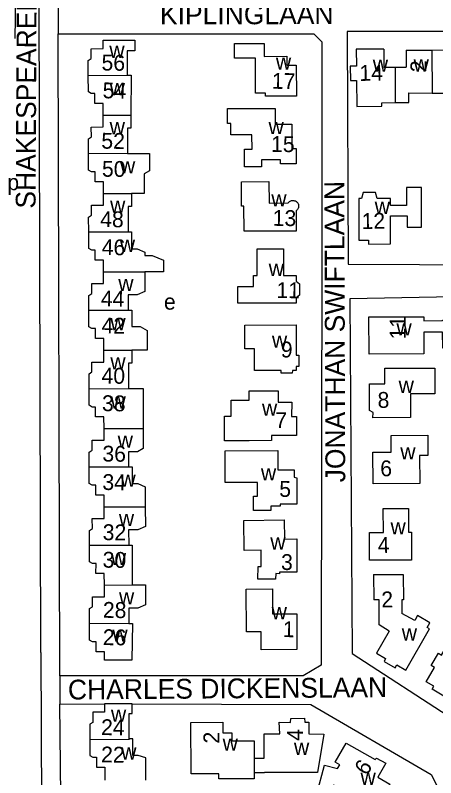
# Model space of a CAD drawing. Extents: x 159441 to 162086, y 388175 to 389787.
# Drawn here: x 161032.2 to 161138.4, y 388501.9 to 388694.6 of the extents above; entities that cross this region are included whole.
import ezdxf

# ---------------------------------------------------------------- set-up
doc = ezdxf.new("R2010")
doc.units = 0
for name, color, linetype in [('BLT_Basislijn', 7, 'Continuous'), ('BLT_Bebouwing', 7, 'Continuous'), ('BLT_Centroide', 7, 'Continuous'), ('BLT_Huisnummer', 7, 'Continuous'), ('BLT_Huisnummer_ tussenligend', 7, 'Continuous'), ('BLT_Onderverdeling_panden', 7, 'Continuous'), ('BLT_Straatnaam', 7, 'Continuous'), ('BLT_Vlakafsluiter', 7, 'Continuous')]:
    doc.layers.add(name, color=color, linetype=linetype)

msp = doc.modelspace()

# ---------------------------------------------------------------- linework, layer by layer
at = {"layer": 'BLT_Basislijn'}
for p, q in [((161032.19, 388688.74), (161032.58, 388714.86)), ((161043.47, 388527.69), (161043.09, 388689.87)), ((161116.02, 388690.48), (161116.31, 388631.73)), ((161165.42, 388623.86), (161116.75, 388622.95)), ((161116.75, 388622.95), (161117.32, 388533.33)), ((161117.32, 388533.33), (161143.65, 388516.17)), ((161043.5, 388520.52), (161054.79, 388520.57)), ((161044.45, 388412.36), (161043.5, 388520.52)), ((161061.74, 388520.59), (161106.86, 388520.45))]:
    msp.add_line(p, q, dxfattribs=at)
for points in [[(161038.68, 388533.55), (161038.25, 388699.64)], [(161043.09, 388689.87), (161107.6, 388689.92), (161109.66, 388687.86), (161109.66, 388636.57)], [(161245.45, 388564.44), (161304.37, 388593.21), (161306.09, 388596.99), (161283.75, 388641.67), (161183.73, 388690.48), (161116.02, 388690.48)], [(161109.66, 388636.57), (161109.49, 388530.39), (161104.96, 388527.66), (161043.47, 388527.69)], [(161116.31, 388631.73), (161170.26, 388631.42), (161224.37, 388604.8), (161245.45, 388564.44)], [(161038.68, 388533.55), (161039.27, 388397.68), (161039.46, 388396.05)], [(161106.86, 388520.45), (161137.31, 388502.69), (161149.7, 388477.9)]]:
    msp.add_lwpolyline(points, dxfattribs=at)
at = {"layer": 'BLT_Bebouwing'}
for p, q in [((161125.32, 388686.07), (161118.36, 388686.03)), ((161125.32, 388686.07), (161125.35, 388681.47)), ((161130.96, 388685.78), (161137.45, 388685.81)), ((161130.96, 388685.78), (161130.99, 388681.49)), ((161137.45, 388685.81), (161143.93, 388685.83)), ((161125.35, 388681.47), (161128.17, 388681.48)), ((161128.17, 388681.48), (161130.99, 388681.49)), ((161089.23, 388671.04), (161097.9, 388671.06)), ((161064.8, 388649.55), (161061.54, 388649.54)), ((161103.17, 388645.2), (161103.17, 388640.05)), ((161122.73, 388553.26), (161122.75, 388546.86)), ((161061.74, 388550.62), (161065.08, 388550.63)), ((161076.63, 388502.89), (161076.59, 388515.86)), ((161092.58, 388506.89), (161095.06, 388506.89)), ((161092.59, 388503.26), (161095.13, 388503.26))]:
    msp.add_line(p, q, dxfattribs=at)
for points in [[(161050.66, 388679.4), (161050.65, 388683.18), (161051.4, 388683.64), (161051.39, 388686.15), (161054.38, 388686.17), (161054.38, 388688.28), (161062.42, 388688.29), (161062.43, 388685.62), (161060.5, 388685.61), (161060.51, 388679.42)], [(161087.58, 388687.48), (161095.09, 388687.5), (161095.1, 388684.18), (161100.81, 388684.22), (161100.85, 388681.95), (161103.21, 388681.98), (161103.26, 388674.19), (161095.45, 388674.17), (161095.44, 388674.94), (161092.9, 388674.93), (161092.86, 388683.78), (161087.57, 388683.76), (161087.58, 388687.48)], [(161118.36, 388686.03), (161118.37, 388681.75), (161116.84, 388681.75), (161116.86, 388678.13), (161118.39, 388678.15), (161118.46, 388671.54)], [(161054.43, 388669.38), (161054.42, 388672.28), (161052.3, 388672.26), (161052.32, 388674.79), (161051.42, 388674.79), (161050.67, 388675.24), (161050.66, 388679.4)], [(161060.51, 388679.42), (161061.45, 388679.43), (161061.43, 388669.39)], [(161128.2, 388672.54), (161131.67, 388672.57), (161131.65, 388674.97), (161137.49, 388674.95)], [(161137.49, 388674.95), (161143.38, 388674.92), (161143.39, 388672.52), (161146.97, 388672.53)], [(161118.46, 388671.54), (161124.82, 388671.6), (161124.81, 388672.51), (161128.2, 388672.54)], [(161097.9, 388671.06), (161097.87, 388667.07), (161102.08, 388667.08), (161102.1, 388660.93), (161103.14, 388660.93), (161103.14, 388657.03), (161099.24, 388657.03), (161099.24, 388658.08), (161094.45, 388658.08), (161094.45, 388656.27), (161090.15, 388656.27), (161090.15, 388660.77), (161092.02, 388660.77), (161091.99, 388664.4), (161086.69, 388664.36), (161086.68, 388667.28), (161085.82, 388667.28), (161085.81, 388671.03), (161089.23, 388671.04)], [(161050.71, 388659.72), (161050.7, 388663.39), (161051.45, 388663.85), (161051.41, 388666.36), (161054.44, 388666.37), (161054.43, 388669.38)], [(161061.43, 388669.39), (161061.42, 388666.06), (161060.56, 388666.06), (161060.57, 388659.63)], [(161054.48, 388649.58), (161054.47, 388652.5), (161052.38, 388652.49), (161052.37, 388655.01), (161051.47, 388655.01), (161050.72, 388655.46), (161050.71, 388659.72)], [(161060.57, 388659.63), (161061.47, 388659.63), (161066.14, 388659.65), (161066.15, 388655.3), (161064.8, 388654.55), (161064.8, 388649.55)], [(161089.33, 388652.54), (161096.3, 388652.55), (161096.31, 388647.14), (161101.18, 388647.18), (161101.33, 388647.36), (161101.48, 388647.5), (161101.62, 388647.6), (161101.78, 388647.67), (161101.96, 388647.75), (161102.15, 388647.79), (161102.33, 388647.8), (161102.57, 388647.79), (161102.79, 388647.73), (161102.96, 388647.67), (161103.1, 388647.6), (161103.22, 388647.53), (161103.36, 388647.39), (161103.47, 388647.27), (161103.6, 388647.09), (161103.64, 388646.99), (161103.73, 388646.8), (161103.77, 388646.62), (161103.78, 388646.48), (161103.79, 388646.3), (161103.75, 388646.1), (161103.73, 388645.96), (161103.67, 388645.81), (161103.59, 388645.67), (161103.49, 388645.5), (161103.42, 388645.42), (161103.34, 388645.33), (161103.26, 388645.27), (161103.17, 388645.2)], [(161103.17, 388640.05), (161090, 388640), (161089.99, 388646.39), (161089.34, 388646.39), (161089.33, 388652.54)], [(161050.76, 388639.83), (161050.75, 388643.6), (161051.5, 388644.06), (161051.49, 388646.58), (161054.49, 388646.59), (161054.48, 388649.58)], [(161061.54, 388649.54), (161061.55, 388646.29), (161060.69, 388646.28), (161060.7, 388639.86)], [(161131.04, 388646.53), (161126.97, 388646.51), (161126.96, 388648.31), (161123.61, 388648.3), (161123.22, 388649.83), (161120.1, 388649.83), (161119.7, 388648.3), (161118.99, 388648.26), (161119.02, 388637.74)], [(161121.46, 388636.77), (161127.01, 388636.82), (161127.02, 388643.88), (161131.21, 388643.87), (161131.2, 388641.05), (161134.84, 388641.04), (161134.86, 388651.05), (161131.05, 388651.05), (161131.04, 388646.53)], [(161054.53, 388629.78), (161054.52, 388632.7), (161052.43, 388632.7), (161052.42, 388635.22), (161051.52, 388635.21), (161050.77, 388635.66), (161050.76, 388639.83)], [(161060.7, 388639.86), (161061.6, 388639.86), (161061.6, 388635.61), (161063.02, 388635.61), (161064.92, 388634.76), (161064.92, 388633.9), (161066.83, 388633.87), (161069.63, 388632.68), (161069.63, 388629.78), (161064.93, 388629.8)], [(161119.02, 388637.74), (161121.44, 388637.75), (161121.46, 388636.77)], [(161093.31, 388635.58), (161099.95, 388635.59), (161099.96, 388628.85), (161103.18, 388628.86), (161103.18, 388627.37), (161104.05, 388626.75), (161104.04, 388623.84), (161103.18, 388623.2), (161103.18, 388621.86), (161088.44, 388621.82), (161088.43, 388626.02), (161092.43, 388626.03), (161092.42, 388628.82), (161093.33, 388628.82), (161093.31, 388635.58)], [(161050.81, 388620.03), (161050.8, 388623.8), (161051.55, 388624.25), (161051.52, 388626.78), (161054.54, 388626.77), (161054.53, 388629.78)], [(161064.93, 388629.8), (161064.94, 388624.77), (161063.03, 388623.91), (161060.73, 388623.91), (161060.74, 388620.05)], [(161054.58, 388609.98), (161054.57, 388612.88), (161052.47, 388612.88), (161052.47, 388615.4), (161051.57, 388615.4), (161050.82, 388615.85), (161050.81, 388620.03)], [(161060.74, 388620.05), (161061.64, 388620.05), (161061.64, 388615.91), (161063.8, 388615.92), (161065.56, 388614.93), (161065.56, 388610), (161061.64, 388609.99)], [(161121.56, 388618.35), (161135.4, 388618.4), (161135.42, 388617.41), (161140.14, 388617.44), (161140.15, 388617.56), (161146.29, 388617.58), (161146.32, 388610.54), (161140.18, 388610.51), (161140.16, 388614.54), (161135.43, 388614.52), (161135.45, 388609.07), (161121.61, 388608.99), (161121.56, 388618.35)], [(161090.22, 388616.31), (161103.2, 388616.33), (161103.2, 388608.74), (161103.88, 388608.72), (161103.88, 388605.86), (161103.21, 388605.85), (161103.2, 388604.85), (161102.22, 388604.85), (161102.19, 388604.15), (161099.34, 388604.15), (161099.34, 388604.84), (161092.62, 388604.82), (161092.61, 388610.32), (161090.21, 388610.31), (161090.22, 388616.31)], [(161050.85, 388600.23), (161050.85, 388603.99), (161051.59, 388604.45), (161051.59, 388606.97), (161054.59, 388606.97), (161054.58, 388609.98)], [(161061.64, 388609.99), (161061.64, 388606.68), (161060.78, 388606.67), (161060.79, 388600.25)], [(161125.55, 388605.42), (161138.19, 388605.43), (161138.19, 388598.94), (161132.05, 388598.93), (161132.06, 388592.94), (161122.57, 388592.89), (161122.58, 388594.18), (161121.67, 388594.73), (161121.67, 388601.42), (161122.55, 388601.42), (161125.55, 388601.43), (161125.55, 388605.42)], [(161054.63, 388590.18), (161054.62, 388593.09), (161052.5, 388593.09), (161052.52, 388595.6), (161051.62, 388595.6), (161050.86, 388596.05), (161050.85, 388600.23)], [(161060.79, 388600.25), (161064.5, 388600.25), (161064.52, 388590.2)], [(161091.27, 388587.09), (161085.03, 388587.08), (161085.03, 388593.25), (161086.79, 388593.25), (161086.79, 388597.31), (161091.27, 388597.33), (161091.26, 388599.67), (161098.65, 388599.68), (161098.66, 388596.79), (161102.05, 388596.8), (161102.03, 388593.2), (161103.23, 388593.18), (161103.23, 388588.39), (161096.93, 388588.4), (161096.94, 388587.1), (161091.27, 388587.09)], [(161050.9, 388580.44), (161050.89, 388584.2), (161051.64, 388584.65), (161051.64, 388587.18), (161054.63, 388587.18), (161054.63, 388590.18)], [(161064.52, 388590.2), (161064.52, 388585.1), (161063.1, 388584.3), (161060.84, 388584.3), (161060.84, 388580.47)], [(161127.15, 388584.2), (161127.17, 388588.43), (161136.4, 388588.46), (161136.41, 388583.36), (161134.35, 388583.35), (161134.37, 388576.3), (161122.58, 388576.19), (161122.51, 388584.16), (161127.15, 388584.2)], [(161085.23, 388584.54), (161098.54, 388584.58), (161098.55, 388579.74), (161102.69, 388579.74), (161102.7, 388577.87), (161103.3, 388577.68), (161103.3, 388571.05), (161099.14, 388571.04), (161099.14, 388570.54), (161096.78, 388570.53), (161096.78, 388569.47), (161092.36, 388569.47), (161092.35, 388573.1), (161093.41, 388573.1), (161093.4, 388576.52), (161085.25, 388576.49), (161085.23, 388584.54)], [(161054.67, 388570.38), (161054.67, 388573.31), (161052.57, 388573.3), (161052.56, 388575.82), (161051.66, 388575.82), (161050.91, 388576.27), (161050.9, 388580.44)], [(161060.84, 388580.47), (161061.74, 388580.47), (161061.74, 388576.24), (161063.15, 388576.24), (161065.05, 388575.39), (161065.06, 388570.4)], [(161065.06, 388570.4), (161065.07, 388565.4), (161063.16, 388564.54), (161060.85, 388564.54), (161060.86, 388560.7)], [(161050.95, 388560.68), (161050.94, 388564.41), (161051.69, 388564.89), (161051.66, 388567.4), (161054.68, 388567.4), (161054.67, 388570.38)], [(161125.18, 388569.92), (161131.51, 388569.93), (161131.51, 388563.93), (161132.31, 388563.93), (161132.31, 388556.93), (161121.71, 388556.92), (161121.7, 388563.9), (161125.23, 388563.91), (161125.18, 388569.92)], [(161089.94, 388566.93), (161100.14, 388567.1), (161100.2, 388562.2), (161103.31, 388562.28), (161103.33, 388553.84), (161098.95, 388553.83), (161098.96, 388553.48), (161098.02, 388553.49), (161097.96, 388552.11), (161093.49, 388552.09), (161093.53, 388555.33), (161094.35, 388555.33), (161094.3, 388559.41), (161090.03, 388559.36), (161089.94, 388566.93)], [(161054.72, 388550.58), (161054.71, 388553.53), (161052.6, 388553.52), (161052.61, 388556.04), (161051.71, 388556.04), (161050.96, 388556.49), (161050.95, 388560.68)], [(161060.86, 388560.7), (161061.76, 388560.7), (161061.74, 388550.62)], [(161122.73, 388553.26), (161130.22, 388553.28), (161130.24, 388546.88), (161129.89, 388546.88), (161129.89, 388543.44)], [(161050.99, 388540.79), (161050.99, 388544.65), (161051.74, 388545.1), (161051.71, 388547.61), (161054.73, 388547.62), (161054.72, 388550.58)], [(161065.08, 388550.63), (161065.09, 388545.63), (161063.19, 388544.76), (161060.88, 388544.76), (161060.89, 388540.92)], [(161090.58, 388549.58), (161097.18, 388549.61), (161097.2, 388543.3), (161103.31, 388543.32), (161103.35, 388534.33), (161094.35, 388534.27), (161094.3, 388538.78), (161090.61, 388538.76), (161090.58, 388549.58)], [(161126.7, 388538.98), (161124.12, 388540.53), (161124.1, 388546.85), (161122.75, 388546.86)], [(161126.7, 388538.98), (161123.49, 388533.35), (161125.76, 388532.06), (161125.38, 388531.31), (161128.18, 388529.69), (161128.6, 388530.41), (161130.88, 388529.13), (161136.84, 388539.55), (161136.27, 388539.87), (161136.97, 388541.09), (161133.85, 388542.87), (161133.16, 388541.66), (161129.89, 388543.44)], [(161060.89, 388540.92), (161061.79, 388540.92), (161061.7, 388531.66), (161054.77, 388531.61), (161054.77, 388533.73), (161052.65, 388533.72), (161052.66, 388536.26), (161051.76, 388536.26), (161051, 388536.7), (161050.99, 388540.79)], [(161142.91, 388522.15), (161140.95, 388523.28), (161140.49, 388522.55), (161137.55, 388524.28), (161137.98, 388525.01), (161136, 388526.17), (161138.09, 388529.77), (161137.29, 388530.24), (161139.11, 388533.36), (161139.9, 388532.9), (161142.01, 388536.51), (161147.41, 388533.37), (161148.46, 388535.18), (161151.95, 388533.15), (161152.39, 388533.42)], [(161054.79, 388520.57), (161054.79, 388518.44), (161051.79, 388518.45), (161051.8, 388515.91), (161051.05, 388515.45), (161051.06, 388511.52)], [(161061.74, 388520.59), (161054.79, 388520.57)], [(161060.97, 388511.72), (161060.95, 388518.14), (161061.74, 388518.15), (161061.74, 388520.59)], [(161095.06, 388512.98), (161099.01, 388513.02), (161098.88, 388515.96), (161101.77, 388515.9), (161101.79, 388516.91), (161105.31, 388516.93), (161105.37, 388515.93), (161106.35, 388515.93), (161106.37, 388512.99), (161110.16, 388512.96), (161108.55, 388503.27), (161106.38, 388503.26), (161098.87, 388503.26), (161095.13, 388503.26)], [(161076.59, 388515.86), (161084.61, 388515.92), (161084.64, 388513.27), (161086.92, 388513.23), (161086.93, 388511.27), (161092.56, 388511.27), (161092.58, 388506.89)], [(161095.06, 388506.89), (161095.06, 388512.98)], [(161051.06, 388511.52), (161051.07, 388507.53), (161051.82, 388507.09), (161052.72, 388507.09), (161052.72, 388504.57), (161054.82, 388504.58), (161054.82, 388501.29)], [(161065.22, 388501.31), (161065.2, 388506.92), (161063.29, 388507.49), (161061.88, 388507.49), (161061.87, 388511.73), (161060.97, 388511.72)], [(161115.81, 388510.66), (161123.13, 388506.48), (161123.43, 388506.89), (161125.78, 388505.59), (161123.76, 388502.03), (161126.81, 388500.29), (161121.27, 388490.57), (161116.61, 388493.23), (161118.51, 388496.56), (161112.56, 388500), (161110.56, 388496.57), (161108.38, 388497.83), (161110.33, 388505.09), (161113.62, 388504.21), (161114.17, 388505.18), (161113.02, 388505.84), (161115.81, 388510.66)], [(161092.59, 388503.26), (161092.59, 388501.63), (161083.62, 388501.6), (161083.61, 388502.91), (161076.63, 388502.89)]]:
    msp.add_lwpolyline(points, dxfattribs=at)
at = {"layer": 'BLT_Onderverdeling_panden'}
for p, q in [((161137.45, 388685.81), (161137.49, 388674.95)), ((161128.17, 388681.48), (161128.2, 388672.54)), ((161050.66, 388679.4), (161060.51, 388679.42)), ((161054.43, 388669.38), (161061.43, 388669.39)), ((161050.71, 388659.72), (161060.57, 388659.63)), ((161054.48, 388649.58), (161061.54, 388649.54)), ((161050.76, 388639.83), (161060.7, 388639.86)), ((161054.53, 388629.78), (161064.93, 388629.8)), ((161050.81, 388620.03), (161060.74, 388620.05)), ((161054.58, 388609.98), (161061.64, 388609.99)), ((161050.85, 388600.23), (161060.79, 388600.25)), ((161054.63, 388590.18), (161064.52, 388590.2)), ((161050.9, 388580.44), (161060.84, 388580.47)), ((161054.67, 388570.38), (161065.06, 388570.4)), ((161050.95, 388560.68), (161060.86, 388560.7)), ((161054.72, 388550.58), (161061.74, 388550.62)), ((161060.89, 388540.92), (161050.99, 388540.79)), ((161092.58, 388506.89), (161092.59, 388503.26))]:
    msp.add_line(p, q, dxfattribs=at)
msp.add_lwpolyline([(161060.97, 388511.72), (161060.97, 388511.55), (161051.06, 388511.52)], dxfattribs=at)
at = {"layer": 'BLT_Vlakafsluiter'}
for p, q in [((161043.07, 388699.59), (161043.09, 388689.87)), ((161043.47, 388527.69), (161043.5, 388520.52))]:
    msp.add_line(p, q, dxfattribs=at)

# ---------------------------------------------------------------- texts
at = {"layer": 'BLT_Centroide'}
for s, p in [('w', (161055.97, 388683.84)), ('w', (161098.05, 388680.84)), ('w', (161122.52, 388680.33)), ('w', (161132.83, 388680.38)), ('w', (161056.05, 388674.39)), ('w', (161056.06, 388664.52)), ('w', (161096.19, 388664.56)), ('w', (161058.66, 388654.62)), ('p', (161030.2, 388650.39)), ('w', (161056.16, 388644.7)), ('w', (161096.89, 388646.28)), ('w', (161123.01, 388644.39)), ('w', (161058.61, 388634.81)), ('w', (161096.23, 388628.72)), ('w', (161058.23, 388624.91)), ('e', (161069.77, 388620.2)), ('w', (161056.22, 388615)), ('w', (161128.5, 388613.69)), ('w', (161097.05, 388610.58)), ('w', (161056.23, 388605.11)), ('w', (161129.05, 388599.16)), ('w', (161056.28, 388595.22)), ('w', (161094.53, 388593.38)), ('w', (161058.08, 388585.31)), ('w', (161129.47, 388582.34)), ('w', (161094.27, 388577.03)), ('w', (161058.77, 388575.44)), ('w', (161058.38, 388565.53)), ('w', (161127, 388563.41)), ('w', (161096.64, 388559.56)), ('w', (161056.36, 388555.64)), ('w', (161058.41, 388545.72)), ('w', (161096.97, 388541.95)), ('w', (161129.84, 388536.59)), ('w', (161056.74, 388536.28)), ('w', (161056.38, 388516.06)), ('w', (161084.59, 388508.75)), ('w', (161102.61, 388507.67)), ('w', (161058.96, 388506.5)), ('w', (161119.42, 388500.11))]:
    msp.add_text(s, height=4, dxfattribs=at).set_placement(p)
at = {"layer": 'BLT_Huisnummer'}
for s, rotation, p in [('56', 359.1344, (161053.98, 388680.65)), ('14', 1.0676, (161119.17, 388678)), ('17', 359.1344, (161097, 388676.03)), ('15', 359.1344, (161096.8, 388660.09)), ('50', 359.1344, (161054.09, 388653.82)), ('13', 359.1344, (161097.21, 388641.4)), ('12', 1.0676, (161119.73, 388640.57)), ('46', 359.1344, (161054.03, 388634.02)), ('11', 359.1344, (161098.15, 388623.16)), ('42', 359.1344, (161053.99, 388614.21)), ('11', 90.0971, (161130.82, 388612.71)), ('9', 359.1344, (161099.26, 388608.14)), ('8', 1.0676, (161123.77, 388595.36)), ('38', 359.1344, (161054.1, 388594.58)), ('7', 359.1344, (161097.85, 388590.28)), ('6', 1.0676, (161124.44, 388578.07)), ('34', 359.1344, (161054.2, 388574.65)), ('5', 359.1344, (161098.87, 388572.9)), ('4', 1.0676, (161123.8, 388558.7)), ('30', 359.1344, (161054.26, 388555.02)), ('3', 359.1344, (161099.32, 388554.43)), ('2', 1.0676, (161124.72, 388544.95)), ('1', 359.1344, (161099.77, 388537.46)), ('26', 359.1344, (161054.31, 388535.44)), ('24', 359.1344, (161053.86, 388512.7)), ('2', 89.1228, (161083.73, 388510.51)), ('4', 89.1228, (161104.83, 388511.22)), ('6', 56.8869, (161120.96, 388502.28))]:
    msp.add_text(s, height=4, rotation=rotation, dxfattribs=at).set_placement(p)
at = {"layer": 'BLT_Huisnummer_ tussenligend'}
for s, rotation, p in [('2', 90.2287, (161136.04, 388680.23)), ('54', 359.1344, (161054.26, 388673.63)), ('52', 359.1344, (161053.93, 388660.9)), ('48', 359.1344, (161053.64, 388641.09)), ('44', 359.1344, (161053.81, 388621.06)), ('40', 359.1344, (161053.98, 388601.54)), ('36', 359.1344, (161054.2, 388581.84)), ('32', 359.1344, (161054.27, 388561.98)), ('28', 359.1344, (161054.32, 388542.34)), ('22', 359.1344, (161053.87, 388505.8))]:
    msp.add_text(s, height=4, rotation=rotation, dxfattribs=at).set_placement(p)
at = {"layer": 'BLT_Straatnaam'}
for s, height, rotation, p in [('SHAKESPEARELAAN', 5, 89.712, (161037.33, 388645.72)), ('KIPLINGLAAN', 5, 0.1151, (161068.77, 388692.28)), ('JONATHAN SWIFTLAAN', 4.9999, 90.2118, (161115.58, 388576.57)), ('CHARLES DICKENSLAAN', 5, 0.4346, (161045.53, 388521.67))]:
    msp.add_text(s, height=height, rotation=rotation, dxfattribs=at).set_placement(p)

doc.saveas('drawing.dxf')
